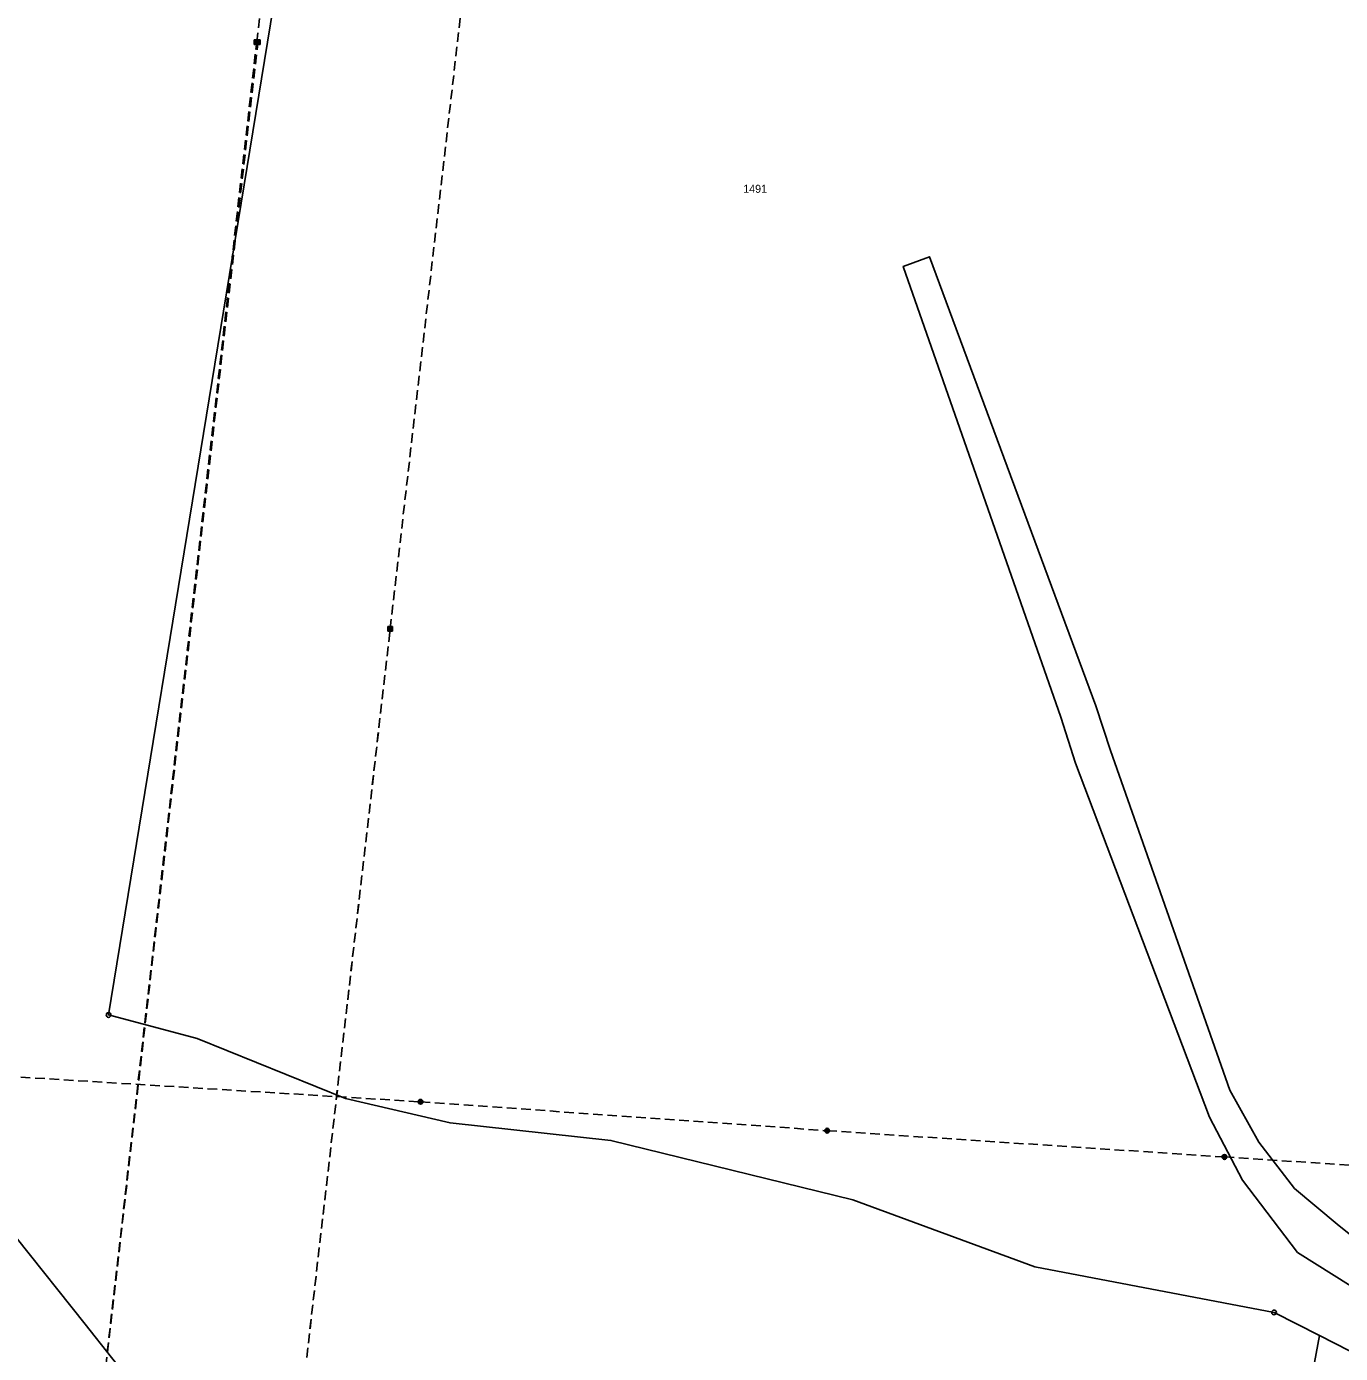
# Model space of a CAD drawing. Extents: x -872229 to -869198, y -1075981 to -1074329.
# Drawn here: x -871865 to -871585.9, y -1075170.8 to -1074889 of the extents above; entities that cross this region are included whole.
import ezdxf

# ---------------------------------------------------------------- set-up
doc = ezdxf.new("R2010")
doc.units = 0
doc.header["$LTSCALE"] = 0.68
doc.linetypes.add('MEDIUM_DASHED', pattern=[4.5, 3, -1.5])
for name, color, linetype, lineweight in [('1', 7, 'Continuous', 25), ('6', 7, 'Continuous', 25), ('8', 7, 'Continuous', 25)]:
    doc.layers.add(name, color=color, linetype=linetype, lineweight=lineweight)
doc.layers.add('2', color=7, linetype='Continuous')

msp = doc.modelspace()

# ---------------------------------------------------------------- linework, layer by layer
at = {"layer": '1'}
for points in [[(-871880.39, -1074773.91), (-871852.19, -1074788.97), (-871835.02, -1074800.17), (-871811.94, -1074817.18), (-871802.66, -1074823.82), (-871825.02, -1074960.68), (-871847.6, -1075098.95), (-871828.77, -1075103.92), (-871797.23, -1075116.69), (-871775.04, -1075121.88), (-871740.88, -1075125.59), (-871689.47, -1075138.24), (-871650.87, -1075152.43), (-871600.02, -1075162.14), (-871590.36, -1075167.06)], [(-871578.94, -1075149.53), (-871586.61, -1075143.41), (-871595.67, -1075135.77), (-871603.22, -1075125.93), (-871609.43, -1075114.89), (-871634.73, -1075042.8), (-871637.87, -1075033.25), (-871673.23, -1074937.88), (-871678.77, -1074939.93), (-871645.3, -1075035.68), (-871642.21, -1075045.44), (-871613.74, -1075120.68), (-871606.71, -1075134.04), (-871595.04, -1075149.42), (-871580.06, -1075158.85)], [(-871852.55, -1075164.62), (-871867.22, -1075146.19), (-871887.9, -1075113.56), (-871891.53, -1075104.31), (-871917.03, -1075102.2)], [(-871829.16, -1075194.06), (-871838.74, -1075182), (-871846.94, -1075171.67), (-871852.55, -1075164.62)], [(-871152.53, -1075228.75), (-871324.15, -1075210.15), (-871498.95, -1075191.88), (-871564.6, -1075180.17), (-871590.36, -1075167.06), (-871608.79, -1075266.42)]]:
    msp.add_lwpolyline(points, dxfattribs=at)
at = {"layer": '6', "linetype": 'MEDIUM_DASHED'}
for p, q in [((-871816.13, -1074892.32), (-871801.92, -1074769.82)), ((-871787.77, -1075016.91), (-871761.64, -1074789.1)), ((-871854.8, -1075231.4), (-871815.86, -1074892.29)), ((-871847.86, -1075170.52), (-871816.13, -1074892.32)), ((-871817.35, -1075275.06), (-871787.76, -1075016.92)), ((-871810.73, -1075217.27), (-871787.77, -1075016.91)), ((-871878.47, -1075111.4), (-871781.31, -1075117.39)), ((-871781.31, -1075117.39), (-871694.96, -1075123.52))]:
    msp.add_line(p, q, dxfattribs=at)
at = {"layer": '6'}
for p, q in [((-871816.632, -1074891.819), (-871815.631, -1074891.819)), ((-871816.632, -1074892.819), (-871816.632, -1074891.819)), ((-871816.632, -1074892.019), (-871815.631, -1074892.019)), ((-871816.632, -1074892.219), (-871815.631, -1074892.219)), ((-871816.431, -1074892.819), (-871816.431, -1074891.819)), ((-871816.362, -1074891.789), (-871815.361, -1074891.789)), ((-871816.362, -1074892.789), (-871816.362, -1074891.789)), ((-871816.362, -1074891.989), (-871815.361, -1074891.989)), ((-871816.362, -1074892.189), (-871815.361, -1074892.189)), ((-871816.232, -1074892.819), (-871816.232, -1074891.819)), ((-871816.161, -1074892.789), (-871816.161, -1074891.789)), ((-871816.031, -1074892.819), (-871816.031, -1074891.819)), ((-871815.962, -1074892.789), (-871815.962, -1074891.789)), ((-871815.832, -1074892.819), (-871815.832, -1074891.819)), ((-871815.761, -1074892.789), (-871815.761, -1074891.789)), ((-871815.631, -1074892.819), (-871815.631, -1074891.819)), ((-871815.562, -1074892.789), (-871815.562, -1074891.789)), ((-871815.361, -1074892.789), (-871815.361, -1074891.789)), ((-871816.632, -1074892.419), (-871815.631, -1074892.419)), ((-871816.632, -1074892.619), (-871815.631, -1074892.619)), ((-871816.632, -1074892.819), (-871815.631, -1074892.819)), ((-871816.362, -1074892.389), (-871815.361, -1074892.389)), ((-871816.362, -1074892.589), (-871815.361, -1074892.589)), ((-871816.362, -1074892.789), (-871815.361, -1074892.789)), ((-871788.272, -1075016.409), (-871787.271, -1075016.409)), ((-871788.272, -1075017.409), (-871788.272, -1075016.409)), ((-871788.272, -1075016.609), (-871787.271, -1075016.609)), ((-871788.272, -1075016.809), (-871787.271, -1075016.809)), ((-871788.272, -1075017.009), (-871787.271, -1075017.009)), ((-871788.272, -1075017.209), (-871787.271, -1075017.209)), ((-871788.272, -1075017.409), (-871787.271, -1075017.409)), ((-871788.262, -1075016.419), (-871787.261, -1075016.419)), ((-871788.262, -1075017.419), (-871788.262, -1075016.419)), ((-871788.262, -1075016.619), (-871787.261, -1075016.619)), ((-871788.262, -1075016.819), (-871787.261, -1075016.819)), ((-871788.262, -1075017.019), (-871787.261, -1075017.019)), ((-871788.262, -1075017.219), (-871787.261, -1075017.219)), ((-871788.262, -1075017.419), (-871787.261, -1075017.419)), ((-871788.071, -1075017.409), (-871788.071, -1075016.409)), ((-871788.061, -1075017.419), (-871788.061, -1075016.419)), ((-871787.872, -1075017.409), (-871787.872, -1075016.409)), ((-871787.862, -1075017.419), (-871787.862, -1075016.419)), ((-871787.671, -1075017.409), (-871787.671, -1075016.409)), ((-871787.661, -1075017.419), (-871787.661, -1075016.419)), ((-871787.472, -1075017.409), (-871787.472, -1075016.409)), ((-871787.462, -1075017.419), (-871787.462, -1075016.419)), ((-871787.271, -1075017.409), (-871787.271, -1075016.409)), ((-871787.261, -1075017.419), (-871787.261, -1075016.419))]:
    msp.add_line(p, q, dxfattribs=at)
at = {"layer": '6', "linetype": 'MEDIUM_DASHED'}
msp.add_lwpolyline([(-871694.96, -1075123.52), (-871610.56, -1075129.11), (-871521.87, -1075134.87)], dxfattribs=at)
at = {"layer": '6'}
for centre, radius in [((-871781.3134, -1075117.3899), 0.5), ((-871781.3134, -1075117.3899), 0.4), ((-871781.3134, -1075117.3899), 0.3), ((-871781.3134, -1075117.3899), 0.2), ((-871781.3134, -1075117.3899), 0.1), ((-871694.9634, -1075123.5199), 0.5), ((-871694.9634, -1075123.5199), 0.4), ((-871694.9634, -1075123.5199), 0.3), ((-871694.9634, -1075123.5199), 0.2), ((-871694.9634, -1075123.5199), 0.1), ((-871610.5634, -1075129.1099), 0.5), ((-871610.5634, -1075129.1099), 0.4), ((-871610.5634, -1075129.1099), 0.3), ((-871610.5634, -1075129.1099), 0.2), ((-871610.5634, -1075129.1099), 0.1)]:
    msp.add_circle(centre, radius, dxfattribs=at)
at = {"layer": '8'}
for centre, radius in [((-871847.6, -1075098.9499), 0.5), ((-871847.6, -1075098.9499), 0.0303), ((-871600.02, -1075162.1399), 0.5), ((-871600.02, -1075162.1399), 0.0303)]:
    msp.add_circle(centre, radius, dxfattribs=at)

# ---------------------------------------------------------------- texts
at = {"layer": '2'}
msp.add_text('1491', height=1.7, dxfattribs=at).set_placement((-871712.78, -1074924.3))

doc.saveas('drawing.dxf')
